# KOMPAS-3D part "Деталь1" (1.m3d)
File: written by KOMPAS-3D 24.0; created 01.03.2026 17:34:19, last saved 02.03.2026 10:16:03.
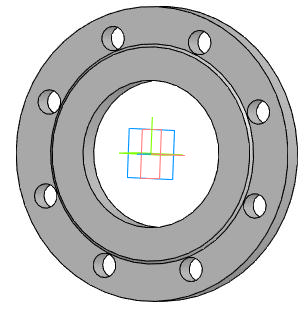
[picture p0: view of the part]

Document properties: Автор: R2D2; Полное имя файла: E:\Работа\Зайцев\GVWR3131M-2W-F-S Задвижка клиновая 30нж64нж DN.ru  Ду50-150 Ру25\исходные данные\DN150\1.m3d

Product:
- Part/product: Деталь1
    Масса: 10.128397
    additional columns: Типовые

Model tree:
1. Эскиз:2
2. Элемент вращения:1
     Угол 1 = 360
3. Эскиз:3  (with: Грань.Элемент вращения:1)
4. Элемент выдавливания:2
     Расстояние 2 = 25
5. Массив по концентрической сетке:1  (with: Элемент выдавливания:2, Эскиз:3, Грань.Элемент вращения:1)  (8 pattern instances)
     Шаг 2 = 360
6. Эскиз:4  (with: Грань.Элемент вращения:1)
7. Элемент выдавливания:3
     Расстояние 2 = 4

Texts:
  Линейный размер с обрывом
